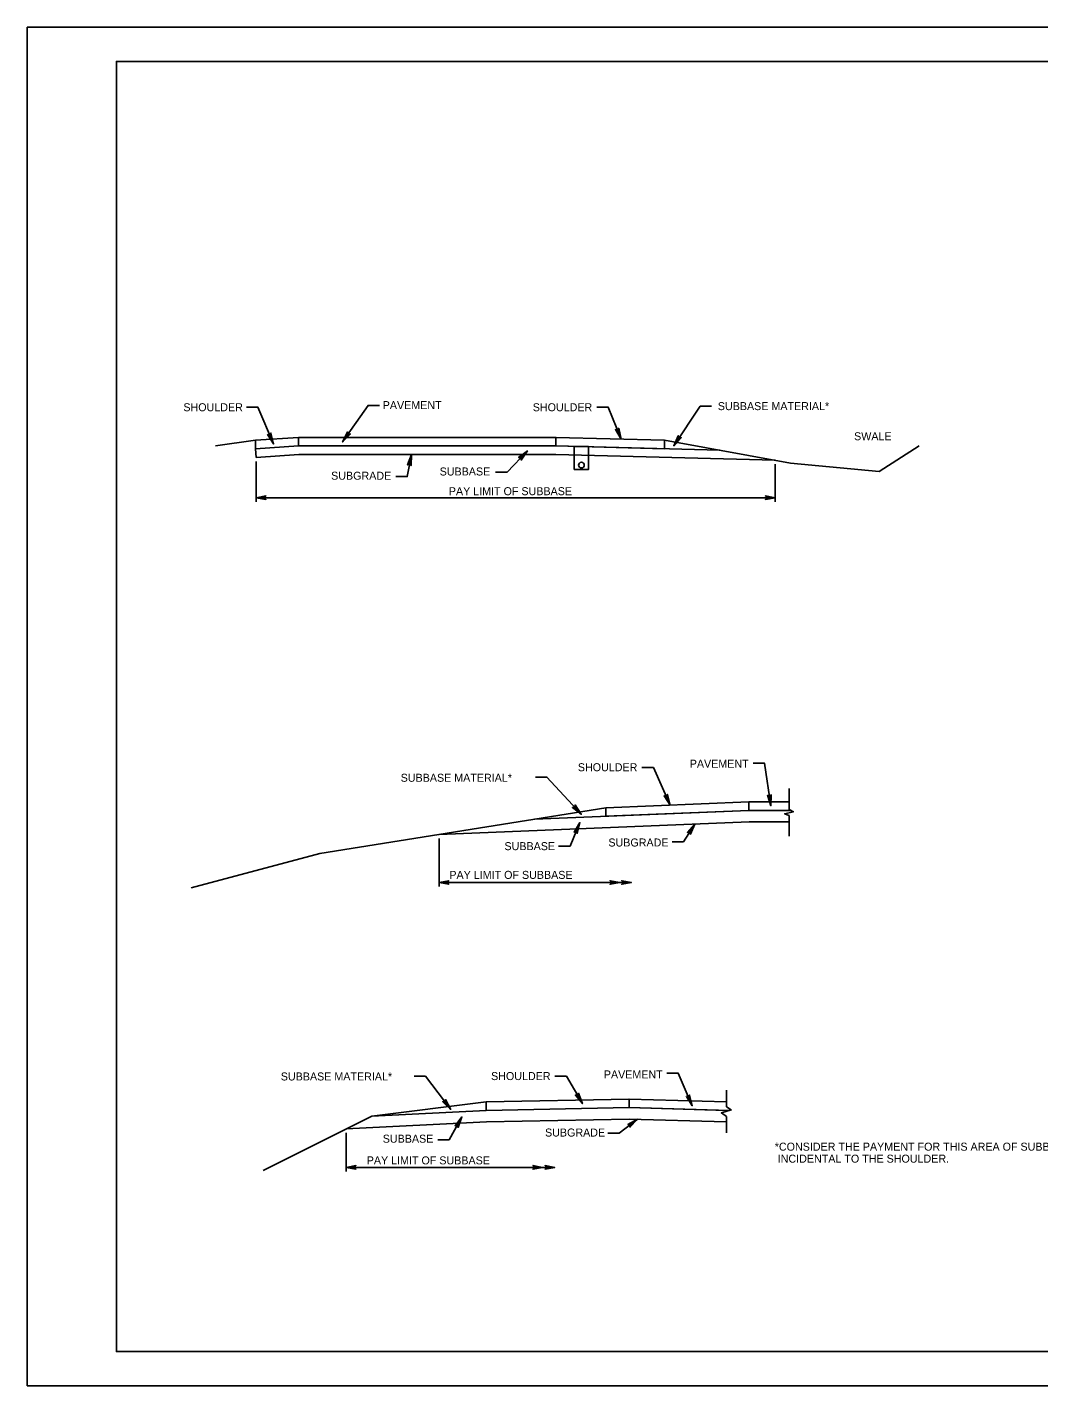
# Model space of a CAD drawing. Extents: x -106 to 798, y -95 to 499.
# Drawn here: x -106 to 336, y -95 to 499 of the extents above; entities that cross this region are included whole.
import ezdxf

# ---------------------------------------------------------------- set-up
doc = ezdxf.new("R2010")
doc.units = 0
for name, color, linetype in [('1', 7, 'Continuous'), ('2', 7, 'Continuous'), ('3', 7, 'Continuous'), ('PLT-BNDY', 7, 'Continuous')]:
    doc.layers.add(name, color=color, linetype=linetype)

msp = doc.modelspace()

# ---------------------------------------------------------------- linework, layer by layer
at = {"layer": '1'}
msp.add_lwpolyline([(719.17, -79.62), (719.17, 484.38), (-66.83, 484.38), (-66.83, -79.62), (719.17, -79.62), (719.17, -53.27), (519.17, -53.27), (519.17, 11.41), (719.17, 11.41), (719.17, 40.38), (519.17, 40.38), (519.17, -79.62), (597.97, -79.62), (597.97, -53.27), (597.97, -79.62), (674.97, -79.62), (674.97, -53.27), (674.97, -65.58), (719.17, -65.58)], dxfattribs=at)
at = {"layer": '2'}
for p, q in [((-5.75, 311.31), (-6, 315.05)), ((-5.75, 309.56), (-5.75, 291.92)), ((220.99, 308.28), (220.99, 291.92)), ((117.3, 293.67), (-5.75, 293.67)), ((220.99, 293.67), (117.3, 293.67)), ((227.12, 166.59), (227.12, 157.32)), ((227.12, 154.69), (227.12, 145.71)), ((74.17, 144.71), (74.17, 123.69)), ((74.17, 125.44), (123.45, 125.44)), ((123.45, 125.44), (158.23, 125.44)), ((199.73, 34.64), (199.73, 27.29)), ((199.73, 23.07), (199.73, 16.04)), ((33.6, 15.96), (33.6, -0.85)), ((33.6, 0.9), (86.12, 0.9)), ((86.12, 0.9), (124.71, 0.9))]:
    msp.add_line(p, q, dxfattribs=at)
for points in [[(-9.96, 333.19), (-4.96, 333.19), (1.82, 317.19)], [(48.15, 334.01), (43.15, 334.01), (32.04, 318.07)], [(143.1, 333.19), (148.1, 333.19), (153.75, 319.3)], [(193.31, 333.74), (188.31, 333.74), (176.72, 316.35)], [(0.57, 321.59), (0.33, 321.3), (1.82, 317.19), (0.57, 321.59), (0.66, 321.88), (1.82, 317.19), (-0.09, 321.12), (-0.45, 321.14), (1.82, 317.19), (-0.74, 321.29), (-0.45, 321.14)], [(35.1, 321.47), (34.74, 321.52), (32.04, 318.07), (35.1, 321.47), (35.4, 321.55), (32.04, 318.07), (34.36, 321.78), (34.19, 322.1), (32.04, 318.07), (34.15, 322.42), (34.19, 322.1)], [(152.57, 323.72), (152.33, 323.44), (153.75, 319.3), (152.57, 323.72), (152.67, 324.01), (153.75, 319.3), (151.91, 323.27), (151.55, 323.29), (153.75, 319.3), (151.25, 323.44), (151.55, 323.29)], [(-6, 318.8), (-23.5, 316.3)], [(-6, 315.05), (12.75, 316.3), (125.25, 316.3), (196.86, 314.42)], [(172.75, 318.8), (227.75, 308.8), (266.5, 305.05), (284, 316.3)], [(179.72, 319.81), (179.35, 319.85), (176.72, 316.35), (179.72, 319.81), (180.01, 319.9), (176.72, 316.35), (178.97, 320.1), (178.78, 320.42), (176.72, 316.35), (178.74, 320.74), (178.78, 320.42)], [(-5.75, 311.31), (12.87, 312.55), (125.2, 312.55), (220.99, 310.03)], [(55.25, 302.9), (60.25, 302.9), (62.07, 312.55)], [(60.67, 308.2), (61.02, 308.3), (62.07, 312.55), (60.67, 308.2), (60.43, 308.01), (62.07, 312.55), (61.47, 308.22), (61.76, 308), (62.07, 312.55), (61.93, 307.72), (61.76, 308)], [(98.9, 304.81), (103.9, 304.81), (112.82, 314.09)], [(109.26, 311.21), (109.61, 311.11), (112.82, 314.09), (109.26, 311.21), (108.96, 311.18), (112.82, 314.09), (109.95, 310.79), (110.07, 310.45), (112.82, 314.09), (110.06, 310.12), (110.07, 310.45)], [(-5.75, 293.67), (-1.53, 294.46), (-1.86, 294.24), (-5.75, 293.67), (-2.02, 293.95), (-2.07, 293.67), (-5.75, 293.67), (-2.02, 293.39), (-1.86, 293.1), (-5.75, 293.67), (-1.53, 292.88), (-1.86, 293.1), (-2.02, 293.39), (-2.07, 293.67), (-2.02, 293.95), (-1.86, 294.24)], [(220.99, 293.67), (216.77, 292.88), (217.09, 293.1), (220.99, 293.67), (217.26, 293.39), (217.31, 293.67), (220.99, 293.67), (217.26, 293.95), (217.09, 294.24), (220.99, 293.67), (216.77, 294.46), (217.09, 294.24), (217.26, 293.95), (217.31, 293.67), (217.26, 293.39), (217.09, 293.1)], [(162.84, 175.66), (167.84, 175.66), (175.19, 159.25)], [(211.43, 177.58), (216.43, 177.58), (219.21, 158.96)], [(116.33, 171.49), (121.33, 171.49), (136.28, 155.29)], [(173.85, 163.63), (173.62, 163.34), (175.19, 159.25), (173.85, 163.63), (173.94, 163.92), (175.19, 159.25), (173.2, 163.15), (172.84, 163.16), (175.19, 159.25), (172.54, 163.3), (172.84, 163.16)], [(228.05, 156.88), (209.62, 156.88), (209.62, 160.63), (227.12, 160.63), (227.12, 160.63)], [(219.1, 163.53), (218.8, 163.31), (219.21, 158.96), (219.1, 163.53), (219.27, 163.79), (219.21, 158.96), (218.35, 163.24), (218.01, 163.35), (219.21, 158.96), (217.76, 163.56), (218.01, 163.35)], [(147.12, 158.13), (22.12, 138.13), (-34.13, 123.13)], [(227.12, 156.88), (209.62, 156.88), (115.87, 153.13)], [(133.62, 159.01), (133.49, 158.66), (136.28, 155.29), (133.62, 159.01), (133.61, 159.32), (136.28, 155.29), (133.16, 158.35), (132.81, 158.25), (136.28, 155.29), (132.49, 158.28), (132.81, 158.25)], [(227.12, 157.32), (229.06, 156.39), (225.18, 155.49), (227.12, 154.69)], [(227.12, 151.88), (209.72, 151.88), (74.17, 146.46)], [(126.44, 141.34), (131.44, 141.34), (135.74, 151.6)], [(133.45, 147.64), (133.82, 147.67), (135.74, 151.6), (133.45, 147.64), (133.18, 147.5), (135.74, 151.6), (134.25, 147.49), (134.49, 147.22), (135.74, 151.6), (134.59, 146.91), (134.49, 147.22)], [(175.99, 143.26), (180.99, 143.26), (185.94, 150.93)], [(183, 147.42), (183.37, 147.39), (185.94, 150.93), (183, 147.42), (182.7, 147.34), (185.94, 150.93), (183.75, 147.14), (183.94, 146.83), (185.94, 150.93), (183.99, 146.51), (183.94, 146.83)], [(74.17, 125.44), (78.4, 126.23), (78.07, 126.01), (74.17, 125.44), (77.9, 125.72), (77.85, 125.44), (74.17, 125.44), (77.9, 125.16), (78.07, 124.87), (74.17, 125.44), (78.4, 124.65), (78.07, 124.87), (77.9, 125.16), (77.85, 125.44), (77.9, 125.72), (78.07, 126.01)], [(153.16, 125.44), (148.94, 124.65), (149.27, 124.87), (153.16, 125.44), (149.43, 125.16), (149.48, 125.44), (153.16, 125.44), (149.43, 125.72), (149.27, 126.01), (153.16, 125.44), (148.94, 126.23), (149.27, 126.01), (149.43, 125.72), (149.48, 125.44), (149.43, 125.16), (149.27, 124.87)], [(158.23, 125.44), (154.01, 124.65), (154.33, 124.87), (158.23, 125.44), (154.5, 125.16), (154.55, 125.44), (158.23, 125.44), (154.5, 125.72), (154.33, 126.01), (158.23, 125.44), (154.01, 126.23), (154.33, 126.01), (154.5, 125.72), (154.55, 125.44), (154.5, 125.16), (154.33, 124.87)], [(173.71, 42), (178.71, 42), (184.84, 27.79)], [(63.23, 40.72), (68.23, 40.72), (79.27, 26.25)], [(124.83, 40.72), (129.83, 40.72), (136.83, 28.77)], [(76.97, 30.2), (76.81, 29.87), (79.27, 26.25), (76.97, 30.2), (76.99, 30.51), (79.27, 26.25), (76.45, 29.59), (76.09, 29.52), (79.27, 26.25), (75.77, 29.58), (76.09, 29.52)], [(157.23, 27.02), (157.23, 30.77), (94.73, 29.52), (94.73, 25.77), (157.23, 27.02)], [(135.03, 32.98), (134.83, 32.67), (136.83, 28.77), (135.03, 32.98), (135.08, 33.28), (136.83, 28.77), (134.44, 32.43), (134.08, 32.41), (136.83, 28.77), (133.76, 32.51), (134.08, 32.41)], [(201.04, 25.73), (157.23, 27.02), (157.23, 30.77), (199.73, 29.52)], [(183.56, 32.19), (183.33, 31.9), (184.84, 27.79), (183.56, 32.19), (183.65, 32.48), (184.84, 27.79), (182.91, 31.71), (182.54, 31.73), (184.84, 27.79), (182.25, 31.87), (182.54, 31.73)], [(94.73, 29.52), (44.73, 23.27), (-2.77, -0.48)], [(199.73, 25.77), (157.23, 27.02), (94.73, 25.77), (44.73, 23.27)], [(199.73, 27.29), (201.89, 25.99), (197.56, 24.69), (199.73, 23.07)], [(199.58, 20.77), (157.2, 22.02), (94.9, 20.77), (33.6, 17.71)], [(73.59, 12.92), (78.59, 12.92), (84.13, 22.92)], [(81.43, 19.22), (81.8, 19.21), (84.13, 22.92), (81.43, 19.22), (81.14, 19.11), (84.13, 22.92), (82.2, 18.99), (82.4, 18.69), (84.13, 22.92), (82.48, 18.37), (82.4, 18.69)], [(147.9, 15.83), (152.9, 15.83), (160.97, 21.91)], [(157, 19.63), (157.34, 19.47), (160.97, 21.91), (157, 19.63), (156.7, 19.65), (160.97, 21.91), (157.61, 19.11), (157.68, 18.75), (160.97, 21.91), (157.62, 18.43), (157.68, 18.75)], [(33.6, 0.9), (37.82, 1.69), (37.5, 1.46), (33.6, 0.9), (37.33, 1.18), (37.28, 0.9), (33.6, 0.9), (37.33, 0.61), (37.5, 0.33), (33.6, 0.9), (37.82, 0.11), (37.5, 0.33), (37.33, 0.61), (37.28, 0.9), (37.33, 1.18), (37.5, 1.46)], [(119.44, 0.86), (115.21, 0.07), (115.54, 0.29), (119.44, 0.86), (115.71, 0.58), (115.76, 0.86), (119.44, 0.86), (115.71, 1.14), (115.54, 1.43), (119.44, 0.86), (115.21, 1.65), (115.54, 1.43), (115.71, 1.14), (115.76, 0.86), (115.71, 0.58), (115.54, 0.29)], [(124.71, 0.9), (120.48, 0.11), (120.81, 0.33), (124.71, 0.9), (120.98, 0.61), (121.03, 0.9), (124.71, 0.9), (120.98, 1.18), (120.81, 1.46), (124.71, 0.9), (120.48, 1.69), (120.81, 1.46), (120.98, 1.18), (121.03, 0.9), (120.98, 0.61), (120.81, 0.33)]]:
    msp.add_lwpolyline(points, dxfattribs=at)
for points in [[(12.75, 316.3), (12.75, 320.05), (-6, 318.8), (-6, 315.05)], [(12.75, 316.3), (12.75, 320.05), (125.25, 320.05), (125.25, 316.3)], [(125.25, 316.3), (125.25, 320.05), (172.75, 318.8), (172.75, 315.05)], [(133.27, 316.02), (133.27, 306.02), (139.52, 306.02), (139.52, 316.02)], [(209.62, 156.88), (209.62, 160.63), (147.12, 158.13), (147.12, 154.38)]]:
    msp.add_lwpolyline(points, close=True, dxfattribs=at)
msp.add_circle((136.4, 307.9), 1.25, dxfattribs=at)
at = {"layer": 'PLT-BNDY'}
msp.add_lwpolyline([(-105.83, 499.38), (735.17, 499.38), (735.17, -94.62), (-105.83, -94.62)], close=True, dxfattribs=at)

# ---------------------------------------------------------------- texts
at = {"layer": '2'}
for p in [(-5.73, 293.4), (220.96, 293.4)]:
    msp.add_text('A', height=0.0165, rotation=180, dxfattribs=at).set_placement(p)
at = {"layer": '3'}
for s, height, p in [('SHOULDER', 3.5, (-37.57, 331.45)), ('PAVEMENT', 3.5, (49.55, 332.38)), ('SHOULDER', 3.5, (115.12, 331.45)), ('SUBBASE MATERIAL*', 3.5, (196.01, 331.95)), ('SWALE', 3.5, (255.55, 318.77)), ('SUBGRADE', 3.5, (27, 301.52)), ('SUBBASE', 3.5, (74.43, 303.37)), ('PAY LIMIT OF SUBBASE', 3.5, (78.44, 294.75)), ('9.07', 0.025, (107.57, 293.38)), ('PAVEMENT', 3.5, (183.74, 175.61)), ('SUBBASE MATERIAL*', 3.5, (57.4, 169.47)), ('SHOULDER', 3.5, (134.83, 174.07)), ('SUBBASE', 3.5, (102.76, 139.57)), ('SUBGRADE', 3.5, (148.18, 141.17)), ('PAY LIMIT OF SUBBASE', 3.5, (78.68, 127.01)), ('SUBBASE MATERIAL*', 3.5, (5.01, 38.88)), ('SHOULDER', 3.5, (96.9, 39.05)), ('PAVEMENT', 3.5, (146.18, 39.77)), ('SUBGRADE', 3.5, (120.49, 14.36)), ('SUBBASE', 3.5, (49.57, 11.67)), ('*CONSIDER THE PAYMENT FOR THIS AREA OF SUBBASE', 3.5, (220.88, 8.19)), (' INCIDENTAL TO THE SHOULDER.', 3.5, (220.88, 2.94)), ('PAY LIMIT OF SUBBASE', 3.5, (42.56, 2.19))]:
    msp.add_text(s, height=height, dxfattribs=at).set_placement(p)

doc.saveas('drawing.dxf')
